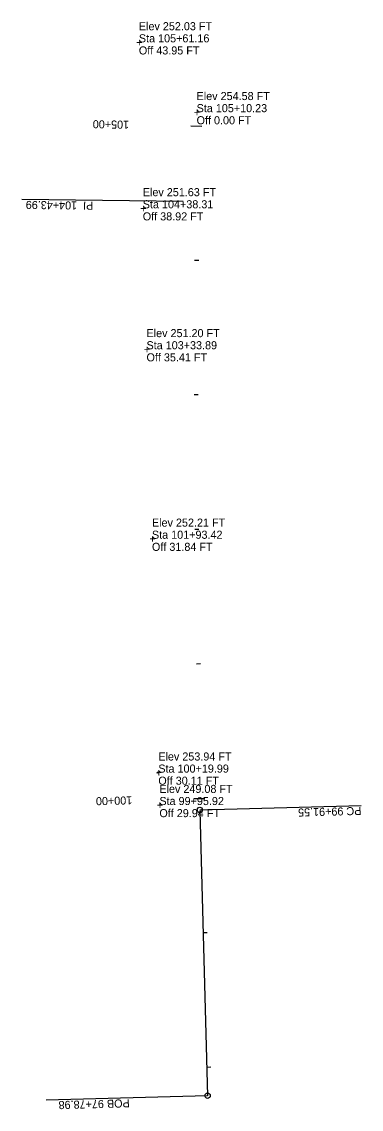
# Model space of a CAD drawing. Extents: x 1930770 to 1938778, y 596900 to 600561.
# Drawn here: x 1930770 to 1931022, y 596900 to 597709 of the extents above; entities that cross this region are included whole.
import ezdxf

# ---------------------------------------------------------------- set-up
doc = ezdxf.new("R2010")
doc.units = 0
for name, color, linetype in [('22', 7, 'Continuous'), ('E_Tract Residual', 7, 'Continuous'), ('S_FENCE_ANNOT', 7, 'Continuous'), ('S_SIDE_DRAIN_ANNOT', 7, 'Continuous'), ('S_STORM_SEWER_ANNOT', 7, 'Continuous')]:
    doc.layers.add(name, color=color, linetype=linetype)

msp = doc.modelspace()

# ---------------------------------------------------------------- linework, layer by layer
at = {"layer": 'E_Tract Residual'}
for points in [[(1930895.32, 597631.32), (1930903.32, 597631.19)], [(1930889.57, 597575.13), (1930769.58, 597576.59)], [(1930901.04, 597531.24), (1930898.04, 597531.26)], [(1930900.64, 597431.26), (1930897.64, 597431.26)], [(1930901.11, 597331.29), (1930898.11, 597331.27)], [(1930902.45, 597231.33), (1930899.45, 597231.27)], [(1930897.66, 597131.19), (1930905.66, 597131.41)], [(1930901.89, 597122.85), (1931021.84, 597126.12)], [(1930907.38, 597031.42), (1930904.38, 597031.34)], [(1930910.1, 596931.46), (1930907.1, 596931.37)], [(1930907.67, 596910.36), (1930787.72, 596907.09)]]:
    msp.add_lwpolyline(points, dxfattribs=at)
for centre in [(1930901.89, 597122.85), (1930907.67, 596910.36)]:
    msp.add_circle(centre, 2, dxfattribs=at)
at = {"layer": 'S_FENCE_ANNOT'}
msp.add_line((1930901.9, 597122.13), (1930907.67, 596910.36), dxfattribs=at)
at = {"layer": 'S_SIDE_DRAIN_ANNOT'}
msp.add_lwpolyline([(1930871, 597150.53), (1930870.5, 597151.03), (1930871, 597150.53), (1930870.5, 597150.03), (1930871, 597150.53), (1930871.5, 597150.03), (1930871, 597150.53), (1930871.5, 597151.03)], dxfattribs=at)

# ---------------------------------------------------------------- texts
at = {"layer": '22'}
for s, p in [('Elev 252.03 FT ', (1930856.59, 597702.39)), ('Sta 105+61.16 ', (1930856.59, 597693.39)), ('Off 43.95 FT  ', (1930856.59, 597684.39)), ('Elev 251.63 FT ', (1930859.51, 597579.03)), ('Sta 104+38.31 ', (1930859.51, 597570.03)), ('Off 38.92 FT  ', (1930859.51, 597561.03)), ('Elev 251.20 FT ', (1930862.27, 597474.24)), ('Sta 103+33.89 ', (1930862.27, 597465.24)), ('Off 35.41 FT  ', (1930862.27, 597456.24)), ('Elev 252.21 FT ', (1930866.32, 597333.37)), ('Sta 101+93.42 ', (1930866.32, 597324.37)), ('Off 31.84 FT  ', (1930866.32, 597315.37)), ('Elev 253.94 FT ', (1930871.05, 597159.53)), ('Sta 100+19.99 ', (1930871.05, 597150.53)), ('Off 30.11 FT  ', (1930871.05, 597141.53)), ('Elev 249.08 FT ', (1930871.84, 597135.42)), ('Sta 99+95.92 ', (1930871.84, 597126.42)), ('Off 29.94 FT  ', (1930871.84, 597117.42))]:
    msp.add_text(s, height=6, dxfattribs=at).set_placement(p)
for rotation, p in [(358.71216, (1930854.56, 597690.43)), (359.32641, (1930857.52, 597567.05)), (359.84853, (1930860.3, 597462.25)), (0.55087, (1930864.39, 597321.36)), (1.41802, (1930869.16, 597147.48)), (1.53834, (1930869.96, 597123.37))]:
    msp.add_text('+', height=6, rotation=rotation, dxfattribs=at).set_placement(p)
at = {"layer": 'E_Tract Residual'}
for s, rotation, p in [('105+00', 179.01794, (1930849.38, 597635.11)), ('PI  104+43.99', 179.29916, (1930822.8, 597574.94)), ('100+00', 181.51794, (1930851.6, 597132.97)), ('PC 99+91.55', 181.56019, (1931021.87, 597125.12)), ('POB 97+78.98', 181.56019, (1930849.71, 596907.78))]:
    msp.add_text(s, height=6, rotation=rotation, dxfattribs=at).set_placement(p)
at = {"layer": 'S_STORM_SEWER_ANNOT'}
for s, p in [('Elev 254.58 FT ', (1930899.5, 597650.48)), ('Sta 105+10.23 ', (1930899.5, 597641.48)), ('Off 0.00 FT  ', (1930899.5, 597632.48))]:
    msp.add_text(s, height=6, dxfattribs=at).set_placement(p)
msp.add_text('+', height=6, rotation=358.96679, dxfattribs=at).set_placement((1930897.49, 597638.52))

doc.saveas('drawing.dxf')
